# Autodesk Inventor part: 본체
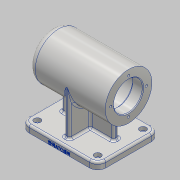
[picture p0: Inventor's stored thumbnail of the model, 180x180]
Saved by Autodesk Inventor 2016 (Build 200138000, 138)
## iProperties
Created: 2020-10
Part Number: 본체
Material: 알루미늄 6061
Document SubType Name: Modeling
Designer: 605-17
Density: 2.7 g/cm^3
Appearance: 알루미늄 - 평지
Mass: 1026.28 g
Surface Area: 757.984 cm^2
Volume: 380.103 cm^3
Author: 605-17
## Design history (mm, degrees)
sketch "스케치1"
  geometry: L1 (56, -45)-(-56, -45); L2 (-56, -45)-(-56, 45); L3 (-56, 45)-(56, 45); L4 (56, 45)-(56, -45); L5 (56, -45)-(-56, 45); L6 (-56, -45)-(56, 45); 1 further point
  constraints: 12 end point, 2 midpoint, 2 parallel, 1 horizontal, 1 perpendicular
  dimensions: "d0" = 112 distance of L2.end L3.end; "d1" = 90 distance of L1.end L2.end
extrude "돌출1" new body sketch "스케치1" distance "d2" = 10; taper "d3" = 0 deg
sketch "스케치2"
  geometry: L1 (56, 74)-(-56, 74); L2 (56, 0)-(-56, 0) reference; L3 (56, 74)-(56, 108); L4 (56, 108)-(-56, 108); L5 (-56, 108)-(-56, 74); L6 (50, 74)-(50, 84.5); L7 (50, 84.5)-(47, 84.5); L8 (47, 84.5)-(47, 90); L9 (47, 90)-(43, 90); L10 (43, 90)-(43, 91.5); L11 (43, 91.5)-(25, 91.5); L12 (25, 91.5)-(25, 95); L13 (25, 95)-(13, 95); L14 (13, 95)-(13, 98); L15 (13, 98)-(-41, 98); L16 (-41, 98)-(-41, 95); L17 (-41, 95)-(-56, 95); 2 further points
  constraints: 32 end point, 12 perpendicular, 2 point on line, 2 vertical, 1 horizontal, 1 midpoint, 1 parallel, 1 vertical alignment
  dimensions: "d4" = 74 distance between parallel lines of L2 L1; "d5" = 3 distance between parallel lines of L8 L6; "d6" = 4 distance between parallel lines of L10 L8; "d7" = 18 distance between parallel lines of L12 L10; "d8" = 12 distance between parallel lines of L14 L12; "d9" = 15 distance between parallel lines of L5 L16; "d10" = 54 distance between parallel lines of L16 L14; "d11" = 112 distance between parallel lines of L5 L3; "d12" = 21 diameter of L7 L1; "d13" = 32 diameter of L9 L1; "d14" = 35 diameter of L11 L1; "d15" = 42 diameter of L13 L1; "d16" = 48 diameter of L15 L1; "d17" = 42 diameter of L17 L1; "d18" = 68 diameter of L4 L1
revolve "회전1" sketch "스케치2" stored, may be unused: angle "d19" = 90 deg
node "작업 평면1"
sketch "스케치3"
  geometry: L1 (4, -34)-(-4, -34); L2 (-4, -34)-(-4, 34); L3 (-4, 34)-(4, 34); L4 (4, 34)-(4, -34); L5 (4, -34)-(-4, 34); L6 (-4, -34)-(4, 34); 1 further point
  constraints: 12 end point, 2 midpoint, 2 parallel, 1 horizontal, 1 perpendicular
  dimensions: "d21" = 68 distance of L3.end L1.start; "d22" = 8 distance of L2.end L3.end
extrude "돌출2" join sketch "스케치3" stored distance "d23" = 10; taper "d24" = 0 deg
sketch "스케치5"
  geometry: L1 (-4, 10)-(-4, 74) reference; L2 (-56, 40)-(56, 40) reference; L3 (-56, 10)-(56, 10) reference; L4 (-38, 40)-(-38, 10); 1 further point
  constraints: 2 end point, 2 point on line, 1 vertical
  dimensions: "d35" = 18 distance of L3.start L4.end
feature "리브2" sketch "스케치5" dims "d36" = 1, "d37" = 8, "d38" = 0, "d39" = 0, "d40" = 1, "d41" = 1
sketch "스케치6"
  geometry: C1 r 34 at (0, 0) reference; 2 further points
  constraints: 1 horizontal alignment
  dimensions: "d42" = 26 distance of C1.centre point (-26, 0)
hole "구멍1" sketch "스케치6" at (-26, 0) diameter "d43" = 3.242; stored, may be unused: countersink angle "d47" = 90 deg, drill point angle "d49" = 118 deg; dims "d44" = 8, "d45" = 4, "d46" = 2, "d48" = 11
fillet "모깎기1" dims "d53" = 3, "d54" = 0.3, "d55" = 10
chamfer "모따기1" distance "d56" = 1; stored, may be unused: second distance "d57" = 2, angle "d58" = 45 deg
fillet "모깎기2" dims "d59" = 12
hole "구멍2" diameter "d63" = 5.5; stored, may be unused: countersink angle "d67" = 90 deg, drill point angle "d69" = 118 deg; dims "d64" = 8, "d65" = 9.5, "d66" = 5.4, "d68" = 11, "d70" = 10, "d71" = 10
hole "구멍3" diameter "d74" = 5.5; stored, may be unused: countersink angle "d78" = 90 deg, drill point angle "d80" = 118 deg; dims "d72" = 10, "d73" = 10, "d75" = 8, "d76" = 9.5, "d77" = 5.4, "d79" = 11
fillet "모깎기4" dims "d81" = 3
fillet "모깎기5" dims "d82" = 3
fillet "모깎기6" dims "d83" = 3
fillet "모깎기7" dims "d84" = 3
sketch "스케치8"
  geometry: L1 (25.59, 5.624)-(62.41, 5.624); L2 (62.41, 5.624)-(62.41, 0.376); L3 (62.41, 0.376)-(25.59, 0.376); L4 (25.59, 0.376)-(25.59, 5.624); L5 (44, 5.624)-(44, 0.376); L6 (44, 3)-(25.59, 3); L7 (100, 0)-(100, 7) reference; 1 further point
  constraints: 4 end point, 4 midpoint, 2 other
  dimensions: "d85" = 56 distance from line of L7 L5.end; "d86" = 3 vertical distance of L7.start L6.start
feature "엠보싱1" sketch "스케치8" dims "d0" = 112, "d1" = 90, "d87" = 0.5, "d88" = 0
node "솔리드1"
mirror "대칭1"
pattern_circular "원형 패턴1" dims angle "d51" = 360 deg
mirror "대칭2"
